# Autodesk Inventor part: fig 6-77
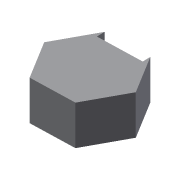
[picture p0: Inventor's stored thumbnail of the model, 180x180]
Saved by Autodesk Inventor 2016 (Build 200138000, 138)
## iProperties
Created: 2009-03
Part Number: fig 6-77
Document SubType Name: Modeling
Designer: Sham
Density: 1 g/cm^3
Material: Generic
Appearance: Default
Author: Sham
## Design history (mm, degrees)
sketch "Sketch5"
  geometry: L1 (-5.929, 9.627)-(5.372, 9.948); L2 (5.372, 9.948)-(11.301, 0.321); L3 (11.301, 0.321)-(5.929, -9.627); L4 (5.929, -9.627)-(-5.372, -9.948); L5 (-5.372, -9.948)-(-11.301, -0.321); L6 (-11.301, -0.321)-(-5.929, 9.627); 1 further point
  constraints: 12 end point, 13 other
extrude "Extrusion3" new body sketch "Sketch5" distance "d13" = 10; taper "d14" = 0 deg
thicken "Thicken2" dims "d15" = 2, "d16" = 2
body "Solid4"
